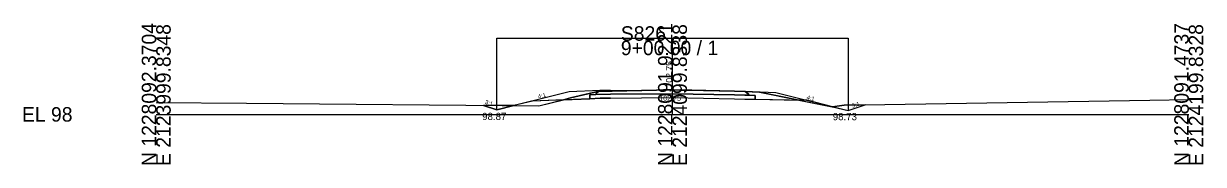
# Model space of a CAD drawing. Extents: x 2118382 to 2118616, y 1213030 to 1222057.
# Drawn here: x 2118381.9 to 2118610.4, y 1219530.1 to 1219557.4 of the extents above; entities that cross this region are included whole.
import ezdxf

# ---------------------------------------------------------------- set-up
doc = ezdxf.new("R2010")
doc.units = 0
for name, color, linetype in [('XS_CELL', 7, 'Continuous'), ('XS_M_DITCH', 7, 'Continuous'), ('XS_M_SHAPES_EARTHWORK', 7, 'Continuous'), ('XS_P_FINISHED_GRADE', 7, 'Continuous'), ('XS_P_FINISHED_GRADE_ELEV_TX', 7, 'Continuous'), ('XS_P_SUBGRADE_GRANULAR', 7, 'Continuous'), ('XS_P_SUBGRADE_PAVEMENT', 7, 'Continuous'), ('XS_P_TX_DCH', 7, 'Continuous'), ('XS_P_TX_FS_BS', 7, 'Continuous'), ('XS_X_GROUND', 7, 'Continuous'), ('XS_X_GROUND_TX', 7, 'Continuous')]:
    doc.layers.add(name, color=color, linetype=linetype)

msp = doc.modelspace()

# ---------------------------------------------------------------- linework, layer by layer
at = {"layer": 'XS_CELL'}
for p, q in [((2118507.6, 1219539.8), (2118507.6, 1219554.07)), ((2118407.6, 1219539.8), (2118507.6, 1219539.8)), ((2118507.6, 1219539.8), (2118607.6, 1219539.8))]:
    msp.add_line(p, q, dxfattribs=at)
at = {"layer": 'XS_M_DITCH'}
for p, q in [((2118473.6, 1219540.68), (2118473.6, 1219554.55)), ((2118473.6, 1219554.55), (2118541.6, 1219554.55)), ((2118541.6, 1219554.55), (2118541.6, 1219540.53))]:
    msp.add_line(p, q, dxfattribs=at)
at = {"layer": 'XS_M_SHAPES_EARTHWORK'}
for p, q in [((2118493.42, 1219544.29), (2118487.87, 1219542.98)), ((2118491.6, 1219543.61), (2118492.73, 1219543.66)), ((2118492.73, 1219543.66), (2118491.6, 1219543.61)), ((2118492.73, 1219543.66), (2118492.91, 1219543.96)), ((2118492.91, 1219543.96), (2118492.73, 1219543.66)), ((2118492.73, 1219543.66), (2118495.6, 1219543.69)), ((2118495.6, 1219543.69), (2118492.73, 1219543.66)), ((2118492.91, 1219543.96), (2118493.42, 1219544.29)), ((2118493.42, 1219544.29), (2118492.91, 1219543.96)), ((2118493.49, 1219544.31), (2118493.42, 1219544.29)), ((2118494.11, 1219544.31), (2118493.49, 1219544.31)), ((2118495.94, 1219544.3), (2118494.11, 1219544.31)), ((2118495.6, 1219543.69), (2118507.6, 1219543.8)), ((2118507.6, 1219543.8), (2118495.6, 1219543.69)), ((2118504.49, 1219544.5), (2118495.94, 1219544.3)), ((2118505.89, 1219544.53), (2118504.49, 1219544.5)), ((2118506.03, 1219544.54), (2118505.89, 1219544.53)), ((2118507.6, 1219544.55), (2118506.03, 1219544.54)), ((2118507.6, 1219543.8), (2118519.6, 1219543.56)), ((2118519.6, 1219543.56), (2118507.6, 1219543.8)), ((2118519.49, 1219544.31), (2118511.38, 1219544.48)), ((2118522.28, 1219543.8), (2118521.68, 1219544.22)), ((2118524.45, 1219544.09), (2118521.68, 1219544.22)), ((2118521.68, 1219544.22), (2118522.28, 1219543.8)), ((2118522.46, 1219543.49), (2118522.28, 1219543.8)), ((2118522.28, 1219543.8), (2118522.46, 1219543.49)), ((2118532.1, 1219542.56), (2118524.45, 1219544.09)), ((2118471, 1219541.54), (2118473.6, 1219540.68)), ((2118476.85, 1219541.49), (2118471, 1219541.54)), ((2118473.6, 1219540.68), (2118476.85, 1219541.49)), ((2118480.46, 1219542.39), (2118476.85, 1219541.49)), ((2118476.85, 1219541.49), (2118481.71, 1219541.44)), ((2118486.46, 1219542.63), (2118480.46, 1219542.39)), ((2118481.71, 1219541.44), (2118486.46, 1219542.63)), ((2118487.87, 1219542.98), (2118486.46, 1219542.63)), ((2118486.46, 1219542.63), (2118491.6, 1219542.84)), ((2118491.6, 1219542.84), (2118491.6, 1219543.61)), ((2118491.6, 1219543.61), (2118491.6, 1219542.84)), ((2118491.6, 1219542.84), (2118493.6, 1219542.92)), ((2118493.6, 1219542.92), (2118495.6, 1219542.94)), ((2118495.6, 1219542.94), (2118507.6, 1219543.05)), ((2118507.6, 1219543.05), (2118519.6, 1219542.81)), ((2118519.6, 1219543.56), (2118521.6, 1219543.52)), ((2118521.6, 1219543.52), (2118519.6, 1219543.56)), ((2118519.6, 1219542.81), (2118521.6, 1219542.77)), ((2118521.6, 1219543.52), (2118522.46, 1219543.49)), ((2118522.46, 1219543.49), (2118521.6, 1219543.52)), ((2118521.6, 1219542.77), (2118523.6, 1219542.73)), ((2118523.6, 1219543.44), (2118522.46, 1219543.49)), ((2118522.46, 1219543.49), (2118523.6, 1219543.44)), ((2118523.6, 1219542.73), (2118523.6, 1219543.44)), ((2118523.6, 1219543.44), (2118523.6, 1219542.73)), ((2118523.6, 1219542.73), (2118532.1, 1219542.56)), ((2118533.6, 1219542.53), (2118532.1, 1219542.56)), ((2118532.1, 1219542.56), (2118538.52, 1219541.28)), ((2118538.58, 1219541.29), (2118533.6, 1219542.53)), ((2118540.87, 1219541.58), (2118538.58, 1219541.29)), ((2118544.93, 1219541.64), (2118540.87, 1219541.58)), ((2118541.6, 1219540.53), (2118544.93, 1219541.64)), ((2118538.52, 1219541.28), (2118538.58, 1219541.29)), ((2118538.58, 1219541.29), (2118541.6, 1219540.53))]:
    msp.add_line(p, q, dxfattribs=at)
for points in [[(2118511.38, 1219544.48), (2118509.34, 1219544.52), (2118507.6, 1219544.55)], [(2118521.68, 1219544.22), (2118519.6, 1219544.31), (2118519.49, 1219544.31)]]:
    msp.add_lwpolyline(points, dxfattribs=at)
at = {"layer": 'XS_P_FINISHED_GRADE'}
for p, q in [((2118487.6, 1219544.18), (2118473.6, 1219540.68)), ((2118493.6, 1219544.42), (2118487.6, 1219544.18)), ((2118495.6, 1219544.44), (2118493.6, 1219544.42)), ((2118495.6, 1219544.44), (2118507.6, 1219544.55)), ((2118507.6, 1219544.55), (2118519.6, 1219544.31)), ((2118519.6, 1219544.31), (2118521.6, 1219544.27)), ((2118521.6, 1219544.27), (2118527.6, 1219544.03)), ((2118527.6, 1219544.03), (2118541.6, 1219540.53)), ((2118473.6, 1219540.68), (2118471, 1219541.54)), ((2118541.6, 1219540.53), (2118544.93, 1219541.64))]:
    msp.add_line(p, q, dxfattribs=at)
at = {"layer": 'XS_P_SUBGRADE_GRANULAR'}
for p, q in [((2118492.73, 1219543.66), (2118491.6, 1219543.61)), ((2118491.6, 1219542.84), (2118480.46, 1219542.39)), ((2118491.6, 1219542.84), (2118491.6, 1219543.61)), ((2118493.6, 1219542.92), (2118491.6, 1219542.84)), ((2118495.6, 1219542.94), (2118493.6, 1219542.92)), ((2118495.6, 1219542.94), (2118507.6, 1219543.05)), ((2118507.6, 1219543.05), (2118519.6, 1219542.81)), ((2118519.6, 1219542.81), (2118521.6, 1219542.77)), ((2118521.6, 1219542.77), (2118523.6, 1219542.73)), ((2118522.46, 1219543.49), (2118523.6, 1219543.44)), ((2118523.6, 1219542.73), (2118523.6, 1219543.44)), ((2118523.6, 1219542.73), (2118533.6, 1219542.53))]:
    msp.add_line(p, q, dxfattribs=at)
at = {"layer": 'XS_P_SUBGRADE_PAVEMENT'}
for p, q in [((2118492.91, 1219543.96), (2118492.73, 1219543.66)), ((2118495.6, 1219543.69), (2118492.73, 1219543.66)), ((2118493.6, 1219544.42), (2118492.91, 1219543.96)), ((2118495.6, 1219543.69), (2118507.6, 1219543.8)), ((2118507.6, 1219543.8), (2118519.6, 1219543.56)), ((2118521.6, 1219544.27), (2118522.28, 1219543.8)), ((2118522.28, 1219543.8), (2118522.46, 1219543.49)), ((2118519.6, 1219543.56), (2118521.6, 1219543.52)), ((2118521.6, 1219543.52), (2118522.46, 1219543.49))]:
    msp.add_line(p, q, dxfattribs=at)
at = {"layer": 'XS_X_GROUND'}
for p, q in [((2118487.87, 1219542.98), (2118493.49, 1219544.31)), ((2118493.49, 1219544.31), (2118494.11, 1219544.31)), ((2118494.11, 1219544.31), (2118495.94, 1219544.3)), ((2118495.94, 1219544.3), (2118504.49, 1219544.5)), ((2118504.49, 1219544.5), (2118505.89, 1219544.53)), ((2118505.89, 1219544.53), (2118507.18, 1219544.56)), ((2118507.18, 1219544.56), (2118507.6, 1219544.55)), ((2118507.6, 1219544.55), (2118509.34, 1219544.52)), ((2118509.34, 1219544.52), (2118511.38, 1219544.48)), ((2118511.38, 1219544.48), (2118518.82, 1219544.34)), ((2118518.82, 1219544.34), (2118524.45, 1219544.09)), ((2118524.45, 1219544.09), (2118538.52, 1219541.28)), ((2118407.6, 1219542.11), (2118425.1, 1219541.98)), ((2118425.1, 1219541.98), (2118481.71, 1219541.44)), ((2118481.71, 1219541.44), (2118487.87, 1219542.98)), ((2118538.52, 1219541.28), (2118540.87, 1219541.58)), ((2118540.87, 1219541.58), (2118600.07, 1219542.55)), ((2118600.07, 1219542.55), (2118607.6, 1219542.7))]:
    msp.add_line(p, q, dxfattribs=at)

# ---------------------------------------------------------------- texts
at = {"layer": 'XS_CELL'}
for s, p in [('N 1228092.3704', (2118407.6, 1219529.8)), ('E 2123999.8348', (2118410.4, 1219529.8)), ('N 1228091.9221', (2118507.6, 1219529.8)), ('E 2124099.8338', (2118510.4, 1219529.8)), ('N 1228091.4737', (2118607.6, 1219529.8)), ('E 2124199.8328', (2118610.4, 1219529.8))]:
    msp.add_text(s, height=2.8, rotation=90, dxfattribs=at).set_placement(p)
for s, p in [('S826', (2118497.6, 1219554.07)), ('9+00.00 / 1', (2118497.6, 1219551.27)), ('EL 98', (2118381.6, 1219538.4))]:
    msp.add_text(s, height=2.8, dxfattribs=at).set_placement(p)
at = {"layer": 'XS_P_FINISHED_GRADE_ELEV_TX'}
msp.add_text(' 102.75', height=1.25, rotation=90, dxfattribs=at).set_placement((2118507.6, 1219544.55))
at = {"layer": 'XS_P_TX_DCH'}
for s, p in [('98.87', (2118470.74, 1219538.7)), ('98.73', (2118538.65, 1219538.67))]:
    msp.add_text(s, height=1.4, dxfattribs=at).set_placement(p)
at = {"layer": 'XS_P_TX_FS_BS'}
for s, rotation, p in [('4:1', 14.0362, (2118481.65, 1219542.84)), ('3:1', 341.5651, (2118471.21, 1219541.88)), ('4:1', 345.9638, (2118533.53, 1219542.76)), ('3:1', 18.4349, (2118542.5, 1219541.06))]:
    msp.add_text(s, height=0.8, rotation=rotation, dxfattribs=at).set_placement(p)
at = {"layer": 'XS_X_GROUND_TX'}
msp.add_text('102.75', height=1, dxfattribs=at).set_placement((2118505.03, 1219542.43))

doc.saveas('drawing.dxf')
